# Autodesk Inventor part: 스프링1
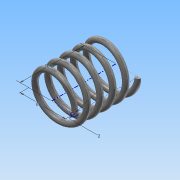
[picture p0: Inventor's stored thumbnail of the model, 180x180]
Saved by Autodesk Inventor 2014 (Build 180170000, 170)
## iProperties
Created: 2016-01
Part Number: 스프링1
Material: 강철, 탄소
Document SubType Name: Modeling
Designer: Administrator
Mass: 6.66264 g
Surface Area: 16.7518 cm^2
Volume: 0.824584 cm^3
Density: 8.08 g/cm^3
Appearance: 반연마
Author: Administrator
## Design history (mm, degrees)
sketch "스케치1"
  geometry: L1 (0, 0)-(8.5, 0); L2 (8.5, 0)-(8.5, 17.5); L3 (8.5, 17.5)-(0, 17.5); L4 (0, 17.5)-(0, 0); C1 r 1 at (8.5, 0)
  constraints: 8 end point, 2 parallel, 1 centre point, 1 coincident, 1 horizontal, 1 perpendicular
  dimensions: "d0" = 2 diameter of C1; "d1" = 17 diameter of L2 L4; "d2" = 17.5 distance of L3.end L1.start (derived)
feature "코일1" sketch "스케치1" pitch "d3" = 10; turns "d5" = 5; dims "d4" = 17.5 (= d2), "d6" = 0, angle "d7" = 90 deg, angle "d8" = 90 deg, "d9" = 0, "d10" = 0
node "작업 평면1"
sketch "스케치2"
  geometry: L1 (-9.5, 0)-(-7.5, 0) reference; 1 further point
  constraints: 1 horizontal alignment
extrude "돌출1" cut sketch "스케치2" distance "d12" = 10; taper "d13" = 0 deg
node "작업 평면2"
sketch "스케치3"
  geometry: L1 (-7.5, 0)-(-9.5, 0) reference; 1 further point
  constraints: 1 horizontal alignment
extrude "돌출2" cut sketch "스케치3" distance "d15" = 10; taper "d16" = 0 deg
node "솔리드1"
node "절단 모서리 투영1"
node "절단 모서리 투영2"
other parameters: "d11" = 17.5 (= d2), "d14" = 0
